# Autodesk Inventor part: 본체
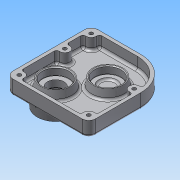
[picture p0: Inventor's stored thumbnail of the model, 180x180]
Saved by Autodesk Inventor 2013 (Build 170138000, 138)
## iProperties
Created: 2015-11
Part Number: 본체
Material: 알루미늄 6061
Document SubType Name: Modeling
Designer: Administrator
Density: 2.71 g/cm^3
Mass: 247.293 g
Surface Area: 390.248 cm^2
Volume: 91.2522 cm^3
Author: Administrator
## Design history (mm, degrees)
sketch "스케치1"
  geometry: L1 (-60, 40)-(-60, -63); L2 (-60, -63)-(40, -63); L3 (40, -63)-(40, 0); L4 (0, 40)-(-60, 40); A1 r 40 centre (0, 0) between (40, 0) and (0, 40); 1 further point
  constraints: 8 end point, 2 coincident, 2 parallel, 2 point on circle, 2 tangent, 1 centre point, 1 perpendicular, 1 vertical
  dimensions: "d0" = 103 distance between parallel lines of L2 L4; "d3" = 100 distance of L1.end L2.end; "d135" = 40 radius of A1
extrude "돌출1" new body sketch "스케치1" distance "d4" = 4; taper "d5" = 0 deg
fillet "모깎기1" dims "d6" = 8
sketch "스케치4"
  geometry: L1 (40, -55)-(40, 0) reference; L2 (0, 40)-(-52, 40) reference; L3 (-60, 32)-(-60, -55) reference; L4 (-52, -63)-(32, -63) reference; L5 (-47.528, 36)-(0, 36); L6 (36, -4.472)-(36, -50.528); L7 (27.528, -59)-(-47.528, -59); L8 (-56, -50.528)-(-56, -4.472); L9 (-56, 4.472)-(-56, 27.528); A1 r 8 centre (32, -55) between (32, -63) and (40, -55) reference; A2 r 40 centre (0, 0) between (40, 0) and (0, 40) reference; A3 r 8 centre (-52, 32) between (-52, 40) and (-60, 32) reference; A4 r 8 centre (-52, -55) between (-60, -55) and (-52, -63) reference; A5 r 36 centre (0, 0) between (35.688, 4.733) and (0, 36); A6 r 6 centre (-52, 32) between (-56, 27.528) and (-47.528, 36); A7 r 6 centre (-52, -55) between (-47.528, -59) and (-56, -50.528); A8 r 6 centre (-52, 0) between (-56, -4.472) and (-56, 4.472); A9 r 6 centre (32, 0) between (35.688, 4.733) and (36, -4.472); A10 r 6 centre (32, -55) between (36, -50.528) and (27.528, -59)
  constraints: 12 point on circle, 10 end point, 6 centre point, 4 coincident, 2 concentric, 2 horizontal alignment, 2 vertical alignment
  dimensions: "d17" = 4 distance between parallel lines of L2 L5; "d18" = 4 distance between parallel lines of L4 L7; "d20" = 12 diameter of A6; "d21" = 12 diameter of A7; "d22" = 12 diameter of A10; "d23" = 12 diameter of A9; "d24" = 12 diameter of A8; "d25" = 84 distance of A9.centre A8.centre; "d26" = 36 radius of A5; "d28" = 4 distance between parallel lines of L1 L6; "d29" = 4 distance between parallel lines of L3 L8; "d30" = 4 distance between parallel lines of L3 L9
extrude "돌출2" join sketch "스케치4" distance "d31" = 14; taper "d32" = 0 deg
sketch "스케치5"
  geometry: C1 r 20 at (0, 0); A1 r 36 centre (0, 0) between (35.688, 4.733) and (0, 36) reference
  constraints: 2 coincident, 1 centre point
  dimensions: "d136" = 40 diameter of C1
extrude "돌출3" join sketch "스케치5" distance "d35" = 11; taper "d36" = -10 deg
sketch "스케치7"
  geometry: C1 r 18.06 at (0, 0) reference; C2 r 16 at (0, 0)
  constraints: 2 coincident, 1 centre point
  dimensions: "d44" = 32 diameter of C2
extrude "돌출4" cut sketch "스케치7" distance "d46" = 9; taper "d47" = 0 deg
sketch "스케치8"
  geometry: C1 r 16 at (0, 0) reference; C2 r 11 at (0, 0)
  constraints: 1 centre point, 1 coincident
  dimensions: "d48" = 22 diameter of C2
extrude "돌출5" cut sketch "스케치8" distance "d50" = 2; taper "d51" = 0 deg
sketch "스케치10"
  geometry: L1 (52, -63)-(-32, -63) reference; L2 (60, 32)-(60, -55) reference; C1 r 25 at (30, -33)
  constraints: 1 centre point
  dimensions: "d55" = 30 distance from line of C1.centre L2; "d56" = 30 distance from line of L1 C1.centre; "d57" = 50 diameter of C1
extrude "돌출6" join sketch "스케치10" distance "d58" = 15; taper "d59" = -10 deg
sketch "스케치11"
  geometry: C1 r 22.355 at (0, 0) reference; 2 further points
  constraints: 1 coincident
hole "구멍2" sketch "스케치11" at (0, 0) diameter "d60" = 24; stored, may be unused: countersink angle "d64" = 90 deg, drill point angle "d66" = 0 deg; dims "d61" = 6, "d62" = 28, "d63" = 11, "d65" = 13
sketch "스케치13"
  geometry: L1 (-60, 32)-(-60, -55) reference; L2 (-52, -63)-(32, -63) reference; C1 r 20 at (-30, -33)
  constraints: 1 centre point
  dimensions: "d71" = 30 distance from line of L1 C1.centre; "d72" = 30 distance from line of C1.centre L2; "d73" = 40 diameter of C1
extrude "돌출8" join sketch "스케치13" distance "d74" = 11; taper "d75" = -10 deg
sketch "스케치16"
  geometry: C1 r 18.06 at (0, 0) reference; 2 further points
  constraints: 1 coincident
hole "구멍3" sketch "스케치16" at (0, 0) diameter "d79" = 20; stored, may be unused: countersink angle "d83" = 90 deg, drill point angle "d85" = 0 deg; dims "d80" = 6, "d81" = 32, "d82" = 9, "d84" = 20
fillet "모깎기2" dims "d107" = 3
fillet "모깎기3" dims "d108" = 3
sketch "스케치21"
  geometry: L1 (-4.887, 23.602)-(44.887, 23.602); L2 (44.887, 23.602)-(44.887, 16.398); L3 (44.887, 16.398)-(-4.887, 16.398); L4 (-4.887, 16.398)-(-4.887, 23.602); L5 (-4.887, 20)-(44.887, 20); L6 (60, -27.689)-(60, 32) reference; L7 (52, 40)-(0, 40) reference; 2 further points
  constraints: 4 midpoint, 2 end point, 1 vertical alignment, 2 other
  dimensions: "d109" = 40 distance from line of L6 point (20, 20); "d110" = 20 distance from line of L7 point (20, 20)
feature "엠보싱1" sketch "스케치21" dims "d111" = 0.5, "d112" = 0
sketch "스케치22"
  geometry: C1 r 14 at (0, 0) reference; 2 further points
  constraints: 1 vertical alignment
  dimensions: "d113" = 18 distance of C1.centre point (0, 18)
hole "구멍4" sketch "스케치22" at (0, 18) diameter "d114" = 2.459; stored, may be unused: countersink angle "d118" = 90 deg, drill point angle "d120" = 118 deg; dims "d115" = 8, "d116" = 32, "d117" = 9, "d119" = 10
chamfer "모따기1" distance "d124" = 1; stored, may be unused: second distance "d125" = 2, angle "d126" = 45 deg
fillet "모깎기4" dims "d127" = 0.3
sketch "스케치26"
  geometry: L1 (42.787, 19.996)-(41.191, 19.996) reference; L2 (41.191, 19.996)-(41.191, 20.452) reference; L3 (41.191, 20.452)-(42.787, 20.452) reference; L4 (42.787, 20.452)-(42.787, 23.545) reference; L5 (42.787, 23.545)-(43.178, 23.545) reference; L6 (43.341, 23.228)-(43.341, 16.422) reference; L7 (43.341, 16.422)-(42.787, 16.422) reference; L8 (42.787, 16.422)-(42.787, 19.996) reference; L9 (3.27, 20.777)-(3.27, 20.305) reference; L10 (3.27, 20.305)-(1.927, 20.305) reference; L11 (1.927, 20.305)-(1.927, 18.213) reference; L12 (1.927, 18.213)-(1.357, 18.213) reference; L13 (1.357, 18.213)-(1.357, 23.602) reference; L14 (1.357, 23.602)-(1.723, 23.602) reference; L15 (1.927, 23.285)-(1.927, 20.777) reference; L16 (1.927, 20.777)-(3.27, 20.777) reference; L17 (2.187, 17.073)-(2.187, 16.617) reference; L18 (2.187, 16.617)-(-3.031, 16.617) reference; L19 (-3.031, 16.617)-(-3.031, 18.571) reference; L20 (-3.031, 18.571)-(-2.608, 18.571) reference; L21 (-2.478, 18.311)-(-2.478, 17.073) reference; L22 (-2.478, 17.073)-(2.187, 17.073) reference; L23 (-0.849, 22.91)-(-2.624, 22.91) reference; L24 (-2.624, 22.91)-(-2.624, 23.334) reference; L25 (-2.624, 23.334)-(-0.849, 23.334) reference; L26 (-0.849, 23.334)-(-0.849, 22.91) reference; L27 (-4.057, 21.942)-(-4.057, 22.365) reference; L28 (-4.057, 22.365)-(0.461, 22.365) reference; L29 (0.461, 22.365)-(0.461, 21.942) reference; L30 (0.461, 21.942)-(-4.057, 21.942) reference; L31 (16.499, 16.862)-(15.832, 18.693) reference; L32 (15.832, 18.693)-(13.129, 18.693) reference; L33 (13.129, 18.693)-(12.445, 16.862) reference; L34 (12.445, 16.862)-(11.867, 16.862) reference; L35 (11.867, 16.862)-(14.147, 22.862) reference; L36 (14.147, 22.862)-(14.798, 22.862) reference; L37 (14.798, 22.862)-(17.077, 16.862) reference; L38 (17.077, 16.862)-(16.499, 16.862) reference; L39 (14.464, 22.275)-(13.316, 19.19) reference; L40 (13.316, 19.19)-(15.636, 19.19) reference; L41 (15.636, 19.19)-(14.464, 22.275) reference; L42 (7.886, 18.978)-(10.06, 18.978) reference; L43 (10.06, 18.978)-(10.06, 16.43) reference; L44 (10.06, 16.43)-(9.506, 16.43) reference; L45 (9.506, 16.43)-(9.506, 18.531) reference; L46 (9.506, 18.531)-(4.906, 18.531) reference; L47 (4.906, 18.531)-(4.906, 18.978) reference; L48 (4.906, 18.978)-(7.341, 18.978) reference; L49 (7.341, 18.978)-(7.341, 20.444) reference; L50 (7.341, 20.444)-(4.027, 20.444) reference; L51 (4.027, 20.444)-(4.027, 20.891) reference; L52 (4.027, 20.891)-(9.27, 20.891) reference; L53 (9.612, 22.894)-(5.045, 22.894) reference; L54 (5.045, 22.894)-(5.045, 23.35) reference; L55 (5.045, 23.35)-(10.19, 23.35) reference; L56 (9.864, 20.891)-(11.232, 20.891) reference; L57 (11.232, 20.891)-(11.232, 20.444) reference; L58 (11.232, 20.444)-(7.886, 20.444) reference; L59 (7.886, 20.444)-(7.886, 18.978) reference; L60 (21.832, 22.862)-(21.832, 22.365) reference; L61 (21.832, 22.365)-(19.959, 22.365) reference; L62 (19.959, 22.365)-(19.959, 16.862) reference; L63 (19.959, 16.862)-(19.414, 16.862) reference; L64 (19.414, 16.862)-(19.414, 22.365) reference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; C1 r 10 at (30, -33) reference; A1 r 5 centre (52, 32) between (57, 32) and (52, 37) reference; A2 r 5 centre (52, -55) between (52, -60) and (57, -55) reference; A3 r 27.517 centre (30, -33) between (35.311, -60) and (57, -38.311) reference; A4 r 37 centre (0, 0) between (0, 37) and (-37, 0) reference; A5 r 5 centre (-32, -55) between (-37, -55) and (-32, -60) reference; A6 r 27.517 centre (30, -33) between (57, -27.689) and (24.689, -60) reference; A7 r 6 centre (-32, 0) between (-32.667, -5.963) and (-31.833, 5.998) reference; A8 r 6 centre (52, 0) between (52.667, 5.963) and (52.667, -5.963) reference; 66 further points
  constraints: 5 coincident, 1 horizontal alignment, 1 vertical alignment, 76 other
hole "구멍5" sketch "스케치26" at (-32, 0), (52, 32), (52, 0), (52, -55), (-32, -55) diameter "d128" = 4.5; stored, may be unused: countersink angle "d132" = 90 deg, drill point angle "d134" = 118 deg; dims "d129" = 6, "d130" = 8, "d131" = 4.4, "d133" = 8
node "솔리드1"
pattern_circular "원형 패턴1" dims angle "d122" = 360 deg
node "절단 모서리 투영3"
other parameters: "d19" = 4
